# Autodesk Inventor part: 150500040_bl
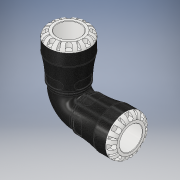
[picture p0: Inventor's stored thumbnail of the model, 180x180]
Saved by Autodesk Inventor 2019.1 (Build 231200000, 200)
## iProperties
Created: 2016-12
Part Number: 150500040_bl
Material: PVC-Piping
Description: PLASSON G-PLASS 90°  ELBOW 40X40
Document SubType Name: Modeling
Designer: KIM
Mass: 664.223 g
Surface Area: 733.008 cm^2
Volume: 474.445 cm^3
Density: 1.4 g/cm^3
Appearance: Black Cast
Author: KIM
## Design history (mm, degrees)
derived "150500.ipt"
feature "Solid1::150500.ipt" dims "ScaleForDerivedMember" = 10
tag "TaggingFeature1"
body "Solid1"
other parameters: "d1" = 31.08 [user parameter], "d8" = 59.5 [user parameter], "d13" = 8 [user parameter], "d14" = 8 [user parameter], "d15" = 0 [user parameter], "d17" = 360 deg [user parameter], "d19" = 8 deg [user parameter], "d20" = 0.8 [user parameter], "d21" = 0.8 [user parameter], "d22" = 8 deg [user parameter], "d24" = 0 [user parameter], "d26" = 360 deg [user parameter], "d33" = 7 [user parameter], "d43" = 54.6 [user parameter], "d51" = 0.7 [user parameter], "d54" = 14 [user parameter], "d55" = 8.8 [user parameter], "d57" = 15.68 [user parameter], "d58" = 0 [user parameter], "d74" = 0 [user parameter], "d77" = 3.33333 [user parameter], "d78" = 74 [user parameter], "d82" = 0.8 [user parameter], "d115" = 360 deg [user parameter], "d207" = 90 deg [user parameter], "d228" = 11.9 [user parameter], "d247" = 1.4 [user parameter], "d248" = 4.44 [user parameter], "d268" = 32.725 [user parameter], "d269" = 4.44 [user parameter], "d270" = 109 [user parameter], "d272" = 90 deg [user parameter], "d274" = 0 [user parameter], "d275" = 0 [user parameter], "l_" = 74 [user parameter], "A_" = 109 [user parameter]
